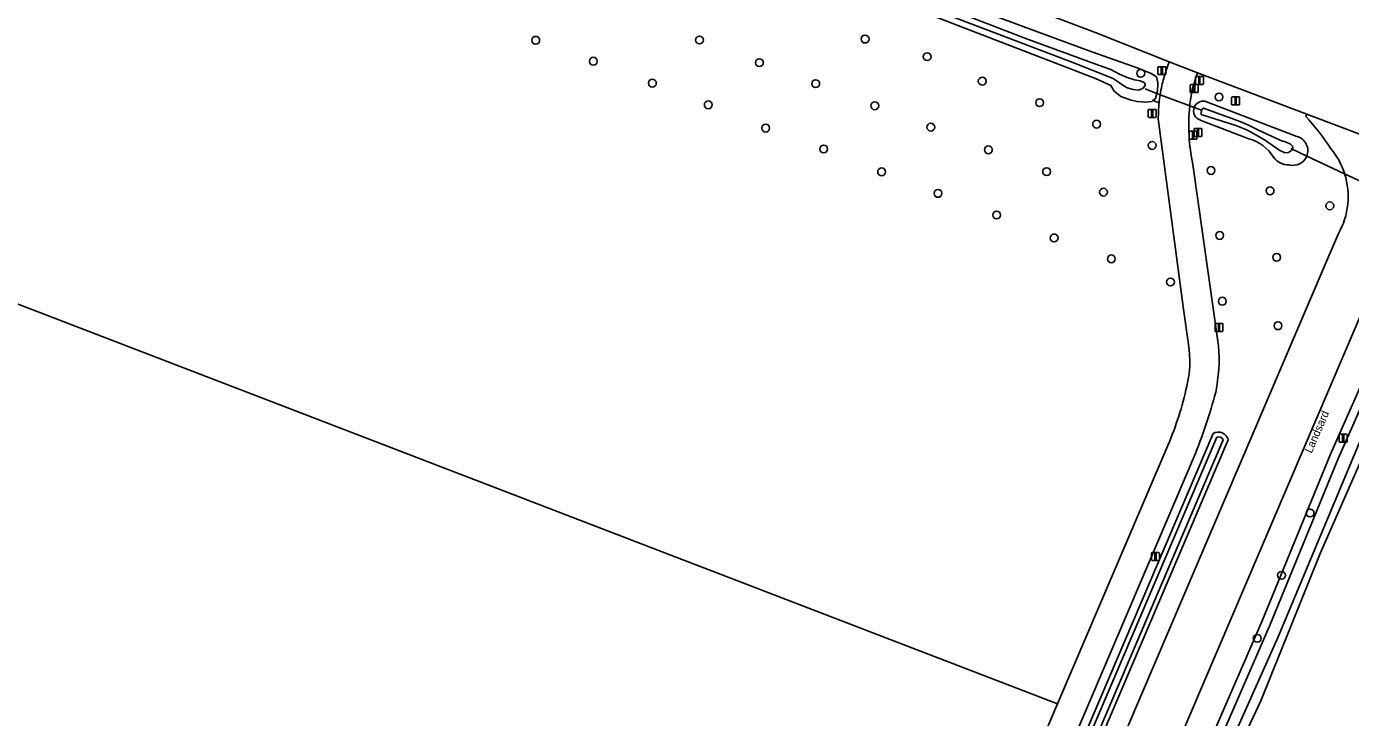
# Model space of a CAD drawing. Extents: x 155209 to 156748, y 385356 to 388487.
# Drawn here: x 155996.7 to 156162.1, y 386488.4 to 386574.7 of the extents above; entities that cross this region are included whole.
import ezdxf

# ---------------------------------------------------------------- set-up
doc = ezdxf.new("R2010")
doc.units = 0
for name, color, linetype in [('IMGEO_Boom', 7, 'Continuous'), ('IMGEO_Bouwland', 7, 'Continuous'), ('IMGEO_Drukknoppaal', 7, 'Continuous'), ('IMGEO_Duiker', 7, 'Continuous'), ('IMGEO_Fietspad_gesloten', 7, 'Continuous'), ('IMGEO_Gemengd_bos', 7, 'Continuous'), ('IMGEO_Groenvoorziening', 7, 'Continuous'), ('IMGEO_Lichtmast', 7, 'Continuous'), ('IMGEO_Oever', 7, 'Continuous'), ('IMGEO_Openbare_ruimte_label', 7, 'Continuous'), ('IMGEO_Portaal', 7, 'Continuous'), ('IMGEO_Rijbaan_lokaal_gesloten', 7, 'Continuous'), ('IMGEO_Verkeersbordpaal', 7, 'Continuous'), ('IMGEO_Verkeersregelinstallatiepaal', 7, 'Continuous'), ('IMGEO_Waterloop', 7, 'Continuous')]:
    doc.layers.add(name, color=color, linetype=linetype)

msp = doc.modelspace()

# ---------------------------------------------------------------- linework, layer by layer
at = {"layer": 'IMGEO_Boom'}
for centre in [(156060.31, 386573.01), (156080.77, 386573.04), (156101.47, 386573.16), (156067.5, 386570.39), (156109.23, 386570.96), (156088.26, 386570.21), (156135.92, 386568.88), (156074.89, 386567.65), (156095.3, 386567.59), (156116.11, 386567.9), (156145.7, 386565.93), (156081.87, 386564.95), (156102.68, 386564.83), (156123.28, 386565.21), (156089.05, 386562.04), (156109.68, 386562.15), (156130.4, 386562.53), (156096.29, 386559.43), (156116.88, 386559.33), (156137.35, 386559.87), (156103.53, 386556.58), (156124.15, 386556.6), (156144.7, 386556.75), (156110.58, 386553.88), (156131.27, 386554.04), (156152.08, 386554.21), (156159.55, 386552.33), (156117.91, 386551.18), (156125.09, 386548.32), (156145.78, 386548.63), (156132.24, 386545.7), (156152.9, 386545.89), (156139.63, 386542.82), (156146.11, 386540.41), (156153.07, 386537.35), (156157.08, 386513.96), (156153.51, 386506.18), (156150.48, 386498.3)]:
    msp.add_circle(centre, 0.489, dxfattribs=at)
at = {"layer": 'IMGEO_Bouwland'}
for points in [[(156137.44, 386565.47), (156137.3, 386565.35), (156136.57, 386565.29), (156135.48, 386565.36), (156134.71, 386565.54), (156133.44, 386566), (156132.58, 386566.64), (156132.19, 386567.35), (156130.25, 386568.22), (156045.7, 386600.84), (156039.21, 386603.34), (156038.99, 386604.12), (156039.24, 386604.81), (156040.24, 386604.88), (156034.05, 386607.74), (156034.11, 386606.65), (156033.86, 386606), (156032.82, 386605.78), (156000, 386618.39), (155978.88, 386626.57)], [(156138.21, 386565.19), (156137.44, 386565.47)], [(156141.9, 386535.02), (156141.28, 386539.44), (156138.11, 386563.18)], [(155948.54, 386558.13), (156125.52, 386490.13), (156139.32, 386522.4)]]:
    msp.add_lwpolyline(points, dxfattribs=at)
msp.add_lwpolyline([(156111.26, 386456.76), (156125.52, 386490.13), (155948.54, 386558.13), (155923.76, 386500), (155881.05, 386399.78), (156052.24, 386324.4), (156054.54, 386323.39), (156054.72, 386323.81), (156066.59, 386351.85), (156087.98, 386402.17)], close=True, dxfattribs=at)
for centre, radius, start, end in [((156157.41, 386563.18), 19.3, 174.0499, 180.0174), ((156128.03, 386532.99), 14.02, 346.9203, 8.3243), ((156099.77, 386539.08), 42.92, 337.1382, 347.5424)]:
    msp.add_arc(centre, radius, start, end, dxfattribs=at)
at = {"layer": 'IMGEO_Drukknoppaal'}
for p, q in [((156142.21, 386567.47), (156143, 386567.47)), ((156143, 386567.47), (156142.21, 386567.47)), ((156142.11, 386566.57), (156142.11, 386567.37)), ((156142.11, 386567.37), (156142.11, 386566.57)), ((156143, 386566.47), (156142.21, 386566.47)), ((156142.21, 386566.47), (156143, 386566.47)), ((156143.1, 386567.37), (156143.1, 386566.57)), ((156143.1, 386566.57), (156143.1, 386567.37))]:
    msp.add_line(p, q, dxfattribs=at)
msp.add_lwpolyline([(156142.53, 386567.35), (156142.68, 386567.35), (156142.68, 386566.6), (156142.53, 386566.6), (156142.53, 386567.35)], dxfattribs=at)
for centre, start, end in [((156142.21, 386567.37), 90, 180), ((156142.21, 386567.37), 90, 180), ((156143, 386567.37), 0, 90), ((156143, 386567.37), 360, 90), ((156142.21, 386566.57), 180, 270), ((156142.21, 386566.57), 180, 270), ((156143, 386566.57), 270, 0), ((156143, 386566.57), 270, 0)]:
    msp.add_arc(centre, 0.1, start, end, dxfattribs=at)
at = {"layer": 'IMGEO_Duiker'}
for points in [[(156143.51, 386564.26), (156142.59, 386564.6), (156142.04, 386564.81), (156138.35, 386566.2), (156137.4, 386566.58), (156136.47, 386566.95)], [(156154.66, 386559.47), (156156.66, 386558.54), (156161.4, 386556.33), (156168.13, 386553.2), (156173, 386550.94), (156177.24, 386548.97)]]:
    msp.add_lwpolyline(points, dxfattribs=at)
at = {"layer": 'IMGEO_Fietspad_gesloten'}
for points in [[(156142.35, 386566.9), (156143.03, 386568.96), (156139.46, 386570.31), (156139.07, 386569.16)], [(156138.11, 386563.18), (156141.28, 386539.44), (156141.9, 386535.02)], [(156145.65, 386534.83), (156142.42, 386557.48)], [(156139.32, 386522.4), (156125.52, 386490.13), (156111.26, 386456.76), (156087.98, 386402.17), (156066.59, 386351.85), (156054.72, 386323.81), (156054.54, 386323.39), (156042.98, 386296.08), (156023.43, 386249.93), (156022.29, 386247.24), (156019.64, 386240.99), (156006.63, 386210.28), (156004.07, 386204.24), (156001.82, 386199.14)], [(156005, 386197.04), (156010, 386208.82), (156023.01, 386239.56), (156046.41, 386294.89), (156058.06, 386322.41), (156069.84, 386350.23), (156091.23, 386400.62), (156114.61, 386455.4), (156142.59, 386521.01)]]:
    msp.add_lwpolyline(points, dxfattribs=at)
for centre, radius, start, end in [((156156.95, 386563.24), 18.84, 161.6813, 167.4703), ((156156.54, 386563.27), 18.43, 170.87, 174.0446), ((156156.73, 386563.29), 18.61, 167.4723, 171.0196), ((156163.24, 386562.68), 21.31, 171.5205, 174.2574), ((156166.66, 386562.21), 24.76, 169.0787, 171.619), ((156157.41, 386563.18), 19.3, 174.0499, 180.0174), ((156165.76, 386562.37), 23.84, 174.1168, 191.8202), ((156128.03, 386532.99), 14.02, 346.9203, 8.3243), ((156124.45, 386533.26), 21.26, 348.5374, 4.2373), ((156099.77, 386539.08), 42.92, 337.1382, 347.5424), ((156082.04, 386545.84), 65.44, 337.7022, 345.1198)]:
    msp.add_arc(centre, radius, start, end, dxfattribs=at)
at = {"layer": 'IMGEO_Gemengd_bos'}
msp.add_lwpolyline([(156205.39, 386417.36), (156200.71, 386439.36), (156193.08, 386476.12), (156190.31, 386491.13), (156187.8, 386507.23), (156186.3, 386514.61), (156186.21, 386515.22), (156185.24, 386523.8), (156181.73, 386545.01), (156177.73, 386546.35), (156176.13, 386545.72), (156173.42, 386543.01), (156172.79, 386541.9), (156167.26, 386529.54), (156163.81, 386521.3), (156158.36, 386508.88), (156150.93, 386490.49), (156141.39, 386470.18), (156096.12, 386365.96)], dxfattribs=at)
at = {"layer": 'IMGEO_Groenvoorziening'}
for points in [[(155877.11, 386667.97), (155902.84, 386658.33), (156000, 386620.97), (156034.05, 386607.74), (156040.24, 386604.88), (156046.53, 386602.9), (156080.99, 386589.91), (156096.99, 386583.72), (156123.14, 386574.02), (156129.81, 386571.56), (156135.61, 386569.52), (156137.2, 386568.86), (156137.88, 386568.44), (156138.05, 386567.68), (156138.04, 386567.52), (156138.02, 386566.69), (156137.76, 386565.73), (156137.44, 386565.47), (156138.21, 386565.19)], [(156139.07, 386569.16), (156139.46, 386570.31), (156130.33, 386573.94), (156122.66, 386576.84), (156047.62, 386605.62)], [(156156.66, 386563.78), (156143.03, 386568.96), (156142.35, 386566.9)], [(156143.94, 386565.39), (156155.43, 386561)], [(156149.43, 386560.71), (156143.34, 386563.05)], [(156156.55, 386563.49), (156156.66, 386563.78)], [(156142.42, 386557.48), (156145.65, 386534.83)], [(156007.59, 386189.1), (156009.57, 386193.77), (156010.6, 386196.2), (156010.67, 386196.17), (156028.11, 386237.4), (156051.19, 386291.96), (156074.96, 386348.06), (156088.15, 386379.28), (156100.53, 386408.28), (156128.81, 386474.42), (156158.86, 386544.7), (156160.63, 386548.86)], [(156063.56, 386292.58), (156064.47, 386293.87), (156065.2, 386295.28), (156082.6, 386339.09), (156140.39, 386475.84), (156151.1, 386500.48), (156159.62, 386521.29), (156166.27, 386536.26), (156169.74, 386543.04), (156171.1, 386545.31)], [(156164.88, 386542.11), (156134.86, 386471.86), (156106.55, 386405.65), (156094.2, 386376.75), (156080.93, 386345.4), (156057.35, 386289.66), (156034.16, 386234.85), (156023.57, 386209.85), (156023.39, 386207.82), (156024.11, 386207.89)], [(156026.29, 386245.49), (156070.68, 386349.65), (156144.95, 386523.89)], [(156146.86, 386523.08), (156072.67, 386349.22), (156028.61, 386244.59)], [(156142.59, 386521.01), (156114.61, 386455.4), (156091.23, 386400.62), (156069.84, 386350.23), (156058.06, 386322.41), (156046.41, 386294.89), (156023.01, 386239.56), (156010, 386208.82), (156005, 386197.04)]]:
    msp.add_lwpolyline(points, dxfattribs=at)
for centre, radius, start, end in [((156156.95, 386563.24), 18.84, 161.6813, 167.4703), ((156156.54, 386563.27), 18.43, 170.87, 174.0446), ((156156.73, 386563.29), 18.61, 167.4723, 171.0196), ((156163.24, 386562.68), 21.31, 171.5205, 174.2574), ((156166.66, 386562.21), 24.76, 169.0787, 171.619), ((156165.76, 386562.37), 23.84, 174.1168, 191.8202), ((156143.72, 386564.19), 1.2, 159.8971, 251.4762), ((156143.73, 386564.2), 1.21, 80.1681, 160.3977), ((156130.28, 386539.78), 35.39, 33.7829, 42.0577), ((156154.95, 386559.22), 1.85, 338.1768, 74.7301), ((156148.05, 386555.67), 5.23, 31.609, 74.681), ((156152.44, 386553.47), 9.41, 17.7403, 39.5755), ((156154.4, 386559.79), 2.35, 216.1722, 271.2872), ((156154.93, 386559.25), 1.87, 255.1017, 337.5493), ((156152.46, 386553.48), 9.38, 330.5109, 17.67), ((156124.45, 386533.26), 21.26, 348.5374, 4.2373), ((156082.04, 386545.84), 65.44, 337.7022, 345.1198), ((156145.61, 386522.78), 1.29, 13.4771, 120.5825)]:
    msp.add_arc(centre, radius, start, end, dxfattribs=at)
at = {"layer": 'IMGEO_Lichtmast'}
for p, q in [((156141.95, 386560.74), (156141.95, 386561.54)), ((156141.95, 386561.54), (156141.95, 386560.74)), ((156142.05, 386561.64), (156142.84, 386561.64)), ((156142.84, 386561.64), (156142.05, 386561.64)), ((156142.94, 386561.54), (156142.94, 386560.74)), ((156142.94, 386560.74), (156142.94, 386561.54)), ((156142.84, 386560.64), (156142.05, 386560.64)), ((156142.05, 386560.64), (156142.84, 386560.64)), ((156145.2, 386536.74), (156145.2, 386537.54)), ((156145.2, 386537.54), (156145.2, 386536.74)), ((156145.3, 386537.64), (156146.09, 386537.64)), ((156146.09, 386537.64), (156145.3, 386537.64)), ((156146.09, 386536.64), (156145.3, 386536.64)), ((156145.3, 386536.64), (156146.09, 386536.64)), ((156146.19, 386537.54), (156146.19, 386536.74)), ((156146.19, 386536.74), (156146.19, 386537.54)), ((156137.26, 386508.14), (156137.26, 386508.93)), ((156137.26, 386508.93), (156137.26, 386508.14)), ((156137.36, 386509.03), (156138.15, 386509.03)), ((156138.15, 386509.03), (156137.36, 386509.03)), ((156138.15, 386508.04), (156137.36, 386508.04)), ((156137.36, 386508.04), (156138.15, 386508.04)), ((156138.25, 386508.93), (156138.25, 386508.14)), ((156138.25, 386508.14), (156138.25, 386508.93))]:
    msp.add_line(p, q, dxfattribs=at)
for points in [[(156142.37, 386561.52), (156142.52, 386561.52), (156142.52, 386560.77), (156142.37, 386560.77), (156142.37, 386561.52)], [(156145.62, 386537.52), (156145.77, 386537.52), (156145.77, 386536.77), (156145.62, 386536.77), (156145.62, 386537.52)], [(156137.68, 386508.91), (156137.83, 386508.91), (156137.83, 386508.16), (156137.68, 386508.16), (156137.68, 386508.91)]]:
    msp.add_lwpolyline(points, dxfattribs=at)
for centre, start, end in [((156142.05, 386561.54), 90, 180), ((156142.05, 386561.54), 90, 180), ((156142.84, 386561.54), 0, 90), ((156142.84, 386561.54), 360, 90), ((156142.05, 386560.74), 180, 270), ((156142.05, 386560.74), 180, 270), ((156142.84, 386560.74), 270, 0), ((156142.84, 386560.74), 270, 0), ((156145.3, 386537.54), 90, 180), ((156145.3, 386537.54), 90, 180), ((156145.3, 386536.74), 180, 270), ((156145.3, 386536.74), 180, 270), ((156146.09, 386537.54), 0, 90), ((156146.09, 386537.54), 360, 90), ((156146.09, 386536.74), 270, 0), ((156146.09, 386536.74), 270, 0), ((156137.36, 386508.93), 90, 180), ((156137.36, 386508.93), 90, 180), ((156137.36, 386508.14), 180, 270), ((156137.36, 386508.14), 180, 270), ((156138.15, 386508.93), 0, 90), ((156138.15, 386508.93), 360, 90), ((156138.15, 386508.14), 270, 0), ((156138.15, 386508.14), 270, 0)]:
    msp.add_arc(centre, 0.1, start, end, dxfattribs=at)
at = {"layer": 'IMGEO_Oever'}
for points in [[(156045.7, 386600.84), (156130.25, 386568.22), (156132.19, 386567.35), (156132.58, 386566.64), (156133.44, 386566), (156134.71, 386565.54), (156135.48, 386565.36), (156136.57, 386565.29), (156137.3, 386565.35), (156137.44, 386565.47), (156137.76, 386565.73), (156138.02, 386566.69), (156138.04, 386567.52), (156138.05, 386567.68), (156137.88, 386568.44), (156137.2, 386568.86), (156135.61, 386569.52), (156129.81, 386571.56), (156123.14, 386574.02), (156096.99, 386583.72)], [(156104.83, 386579.74), (156121.45, 386573.27), (156130.64, 386569.91), (156132.19, 386569.37), (156133.25, 386568.78), (156134.21, 386568.35), (156135.14, 386568.07), (156135.86, 386567.93), (156136.34, 386567.72), (156136.5, 386567.45), (156136.2, 386567.03), (156135.67, 386566.79), (156134.96, 386566.86), (156134.23, 386567.07), (156133.55, 386567.49), (156132.49, 386568.24), (156127.43, 386570.23), (156106.38, 386578.26)], [(156155.43, 386561), (156143.94, 386565.39)], [(156143.34, 386563.05), (156149.43, 386560.71)], [(156123.57, 386433.22), (156141.4, 386475.41), (156152.11, 386500.05), (156160.63, 386520.86), (156167.26, 386535.78), (156170.7, 386542.51), (156172, 386544.66), (156173.01, 386545.83), (156173.54, 386546.4), (156175.33, 386547.03), (156173.2, 386547.64), (156172.2, 386546.57), (156171.1, 386545.31), (156169.74, 386543.04), (156166.27, 386536.26), (156159.62, 386521.29), (156151.1, 386500.48), (156140.39, 386475.84), (156082.6, 386339.09), (156065.2, 386295.28), (156064.47, 386293.87), (156063.56, 386292.58)], [(156096.12, 386365.96), (156141.39, 386470.18), (156150.93, 386490.49), (156158.36, 386508.88), (156163.81, 386521.3), (156167.26, 386529.54), (156172.79, 386541.9), (156173.42, 386543.01), (156176.13, 386545.72), (156177.73, 386546.35), (156176.15, 386546.8), (156174.87, 386546.02), (156172.95, 386543.96), (156170.88, 386540.42), (156164.5, 386525.78), (156153.08, 386498.49), (156141.69, 386472.93), (156117.96, 386417.73), (156104.89, 386387.44)], [(156144.95, 386523.89), (156070.68, 386349.65), (156026.29, 386245.49)], [(156026.79, 386245.14), (156071.23, 386349.41), (156145.41, 386523.44)], [(156146.22, 386523.1), (156072.12, 386349.46), (156027.95, 386244.58)], [(156028.61, 386244.59), (156072.67, 386349.22), (156146.86, 386523.08)]]:
    msp.add_lwpolyline(points, dxfattribs=at)
msp.add_lwpolyline([(156147.77, 386563.07), (156148.65, 386562.72), (156149.38, 386562.4), (156150.54, 386561.82), (156153.43, 386560.48), (156154.09, 386560.3), (156154.62, 386560.05), (156154.89, 386559.78), (156154.93, 386559.54), (156154.75, 386559.24), (156154.39, 386559.01), (156153.95, 386558.95), (156153.31, 386559.26), (156152.76, 386559.62), (156151.37, 386560.57), (156149.24, 386561.76), (156147.81, 386562.35), (156143.47, 386563.72), (156143.47, 386563.99), (156143.54, 386564.35), (156143.74, 386564.53)], close=True, dxfattribs=at)
for centre, radius, start, end in [((156143.72, 386564.19), 1.2, 159.8971, 251.4762), ((156143.73, 386564.2), 1.21, 80.1681, 160.3977), ((156154.95, 386559.22), 1.85, 338.1768, 74.7301), ((156148.05, 386555.67), 5.23, 31.609, 74.681), ((156154.4, 386559.79), 2.35, 216.1722, 271.2872), ((156154.93, 386559.25), 1.87, 255.1017, 337.5493), ((156145.61, 386522.78), 1.29, 13.4771, 120.5825), ((156145.61, 386522.78), 0.693, 27.6005, 106.5491)]:
    msp.add_arc(centre, radius, start, end, dxfattribs=at)
at = {"layer": 'IMGEO_Portaal'}
for p, q in [((156147.28, 386565.03), (156147.28, 386565.83)), ((156147.28, 386565.83), (156147.28, 386565.03)), ((156147.38, 386565.93), (156148.17, 386565.93)), ((156148.17, 386565.93), (156147.38, 386565.93)), ((156148.27, 386565.83), (156148.27, 386565.03)), ((156148.27, 386565.03), (156148.27, 386565.83)), ((156148.17, 386564.93), (156147.38, 386564.93)), ((156147.38, 386564.93), (156148.17, 386564.93))]:
    msp.add_line(p, q, dxfattribs=at)
msp.add_lwpolyline([(156147.7, 386565.8), (156147.85, 386565.8), (156147.85, 386565.05), (156147.7, 386565.05), (156147.7, 386565.8)], dxfattribs=at)
for centre, start, end in [((156147.38, 386565.83), 90, 180), ((156147.38, 386565.83), 90, 180), ((156148.17, 386565.83), 0, 90), ((156148.17, 386565.83), 360, 90), ((156147.38, 386565.03), 180, 270), ((156147.38, 386565.03), 180, 270), ((156148.17, 386565.03), 270, 0), ((156148.17, 386565.03), 270, 0)]:
    msp.add_arc(centre, 0.1, start, end, dxfattribs=at)
at = {"layer": 'IMGEO_Rijbaan_lokaal_gesloten'}
for points in [[(156122.66, 386576.84), (156130.33, 386573.94), (156139.46, 386570.31), (156143.03, 386568.96), (156156.66, 386563.78), (156162.51, 386561.56)], [(156181.95, 386553.84), (156182.05, 386554.14), (156162.51, 386561.56), (156156.66, 386563.78), (156156.55, 386563.49)], [(156160.63, 386548.86), (156158.86, 386544.7), (156128.81, 386474.42), (156100.53, 386408.28), (156088.15, 386379.28), (156074.96, 386348.06), (156051.19, 386291.96), (156028.11, 386237.4), (156010.67, 386196.17), (156016.71, 386193.64), (156023.57, 386209.85), (156034.16, 386234.85), (156057.35, 386289.66), (156080.93, 386345.4), (156094.2, 386376.75), (156106.55, 386405.65)], [(156106.55, 386405.65), (156134.86, 386471.86), (156164.88, 386542.11)]]:
    msp.add_lwpolyline(points, dxfattribs=at)
for centre, radius, start, end in [((156130.28, 386539.78), 35.39, 33.7829, 42.0577), ((156152.44, 386553.47), 9.41, 17.7403, 39.5755), ((156152.46, 386553.48), 9.38, 330.5109, 17.67)]:
    msp.add_arc(centre, radius, start, end, dxfattribs=at)
at = {"layer": 'IMGEO_Verkeersbordpaal'}
for p, q in [((156136.86, 386563.48), (156136.86, 386564.28)), ((156136.86, 386564.28), (156136.86, 386563.48)), ((156136.96, 386564.38), (156137.75, 386564.38)), ((156137.75, 386564.38), (156136.96, 386564.38)), ((156137.85, 386564.28), (156137.85, 386563.48)), ((156137.85, 386563.48), (156137.85, 386564.28)), ((156137.75, 386563.38), (156136.96, 386563.38)), ((156136.96, 386563.38), (156137.75, 386563.38)), ((156142.58, 386561.09), (156142.58, 386561.89)), ((156142.58, 386561.89), (156142.58, 386561.09)), ((156142.68, 386561.99), (156143.47, 386561.99)), ((156143.47, 386561.99), (156142.68, 386561.99)), ((156143.47, 386560.99), (156142.68, 386560.99)), ((156142.68, 386560.99), (156143.47, 386560.99)), ((156143.57, 386561.89), (156143.57, 386561.09)), ((156143.57, 386561.09), (156143.57, 386561.89)), ((156160.72, 386522.89), (156160.72, 386523.69)), ((156160.72, 386523.69), (156160.72, 386522.89)), ((156160.82, 386523.79), (156161.61, 386523.79)), ((156161.61, 386523.79), (156160.82, 386523.79)), ((156161.61, 386522.79), (156160.82, 386522.79)), ((156160.82, 386522.79), (156161.61, 386522.79)), ((156161.71, 386523.69), (156161.71, 386522.89)), ((156161.71, 386522.89), (156161.71, 386523.69))]:
    msp.add_line(p, q, dxfattribs=at)
for points in [[(156137.28, 386564.25), (156137.43, 386564.25), (156137.43, 386563.5), (156137.28, 386563.5), (156137.28, 386564.25)], [(156143, 386561.86), (156143.15, 386561.86), (156143.15, 386561.11), (156143, 386561.11), (156143, 386561.86)], [(156161.14, 386523.67), (156161.29, 386523.67), (156161.29, 386522.92), (156161.14, 386522.92), (156161.14, 386523.67)]]:
    msp.add_lwpolyline(points, dxfattribs=at)
for centre, start, end in [((156136.96, 386564.28), 90, 180), ((156136.96, 386564.28), 90, 180), ((156137.75, 386564.28), 0, 90), ((156137.75, 386564.28), 360, 90), ((156136.96, 386563.48), 180, 270), ((156136.96, 386563.48), 180, 270), ((156137.75, 386563.48), 270, 0), ((156137.75, 386563.48), 270, 0), ((156142.68, 386561.89), 90, 180), ((156142.68, 386561.89), 90, 180), ((156142.68, 386561.09), 180, 270), ((156142.68, 386561.09), 180, 270), ((156143.47, 386561.89), 0, 90), ((156143.47, 386561.89), 360, 90), ((156143.47, 386561.09), 270, 0), ((156143.47, 386561.09), 270, 0), ((156160.82, 386523.69), 90, 180), ((156160.82, 386523.69), 90, 180), ((156160.82, 386522.89), 180, 270), ((156160.82, 386522.89), 180, 270), ((156161.61, 386523.69), 0, 90), ((156161.61, 386523.69), 360, 90), ((156161.61, 386522.89), 270, 0), ((156161.61, 386522.89), 270, 0)]:
    msp.add_arc(centre, 0.1, start, end, dxfattribs=at)
at = {"layer": 'IMGEO_Verkeersregelinstallatiepaal'}
for p, q in [((156138.07, 386568.82), (156138.07, 386569.61)), ((156138.07, 386569.61), (156138.07, 386568.82)), ((156138.17, 386569.71), (156138.96, 386569.71)), ((156138.96, 386569.71), (156138.17, 386569.71)), ((156139.06, 386569.61), (156139.06, 386568.82)), ((156139.06, 386568.82), (156139.06, 386569.61)), ((156138.96, 386568.72), (156138.17, 386568.72)), ((156138.17, 386568.72), (156138.96, 386568.72)), ((156142.75, 386567.6), (156142.75, 386568.4)), ((156142.75, 386568.4), (156142.75, 386567.6)), ((156142.85, 386568.5), (156143.64, 386568.5)), ((156143.64, 386568.5), (156142.85, 386568.5)), ((156143.64, 386567.5), (156142.85, 386567.5)), ((156142.85, 386567.5), (156143.64, 386567.5)), ((156143.74, 386568.4), (156143.74, 386567.6)), ((156143.74, 386567.6), (156143.74, 386568.4))]:
    msp.add_line(p, q, dxfattribs=at)
for points in [[(156138.49, 386569.59), (156138.64, 386569.59), (156138.64, 386568.84), (156138.49, 386568.84), (156138.49, 386569.59)], [(156143.17, 386568.38), (156143.32, 386568.38), (156143.32, 386567.63), (156143.17, 386567.63), (156143.17, 386568.38)]]:
    msp.add_lwpolyline(points, dxfattribs=at)
for centre, start, end in [((156138.17, 386569.61), 90, 180), ((156138.17, 386569.61), 90, 180), ((156138.96, 386569.61), 0, 90), ((156138.96, 386569.61), 360, 90), ((156138.17, 386568.82), 180, 270), ((156138.17, 386568.82), 180, 270), ((156138.96, 386568.82), 270, 0), ((156138.96, 386568.82), 270, 0), ((156142.85, 386568.4), 90, 180), ((156142.85, 386568.4), 90, 180), ((156142.85, 386567.6), 180, 270), ((156142.85, 386567.6), 180, 270), ((156143.64, 386568.4), 0, 90), ((156143.64, 386568.4), 360, 90), ((156143.64, 386567.6), 270, 0), ((156143.64, 386567.6), 270, 0)]:
    msp.add_arc(centre, 0.1, start, end, dxfattribs=at)
at = {"layer": 'IMGEO_Waterloop'}
for points in [[(156106.38, 386578.26), (156127.43, 386570.23), (156132.49, 386568.24), (156133.55, 386567.49), (156134.23, 386567.07), (156134.96, 386566.86), (156135.67, 386566.79), (156136.2, 386567.03), (156136.5, 386567.45), (156136.34, 386567.72), (156135.86, 386567.93), (156135.14, 386568.07), (156134.21, 386568.35), (156133.25, 386568.78), (156132.19, 386569.37), (156130.64, 386569.91), (156121.45, 386573.27), (156104.83, 386579.74)], [(156104.89, 386387.44), (156117.96, 386417.73), (156141.69, 386472.93), (156153.08, 386498.49), (156164.5, 386525.78), (156170.88, 386540.42), (156172.95, 386543.96), (156174.87, 386546.02), (156176.15, 386546.8), (156175.33, 386547.03), (156173.54, 386546.4), (156173.01, 386545.83), (156172, 386544.66), (156170.7, 386542.51), (156167.26, 386535.78), (156160.63, 386520.86), (156152.11, 386500.05), (156141.4, 386475.41), (156123.57, 386433.22), (156107.37, 386395.72)], [(156145.41, 386523.44), (156071.23, 386349.41), (156026.79, 386245.14)], [(156027.95, 386244.58), (156072.12, 386349.46), (156146.22, 386523.1)]]:
    msp.add_lwpolyline(points, dxfattribs=at)
msp.add_lwpolyline([(156147.77, 386563.07), (156143.74, 386564.53), (156143.54, 386564.35), (156143.47, 386563.99), (156143.47, 386563.72), (156147.81, 386562.35), (156149.24, 386561.76), (156151.37, 386560.57), (156152.76, 386559.62), (156153.31, 386559.26), (156153.95, 386558.95), (156154.39, 386559.01), (156154.75, 386559.24), (156154.93, 386559.54), (156154.89, 386559.78), (156154.62, 386560.05), (156154.09, 386560.3), (156153.43, 386560.48), (156150.54, 386561.82), (156149.38, 386562.4), (156148.65, 386562.72)], close=True, dxfattribs=at)
msp.add_arc((156145.61, 386522.78), 0.693, 27.6005, 106.5491, dxfattribs=at)

# ---------------------------------------------------------------- texts
at = {"layer": 'IMGEO_Openbare_ruimte_label'}
msp.add_text('Landsard', height=1, rotation=66.5608, dxfattribs=at).set_placement((156157.27, 386521.35))

doc.saveas('drawing.dxf')
